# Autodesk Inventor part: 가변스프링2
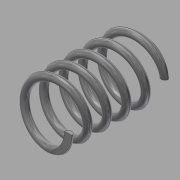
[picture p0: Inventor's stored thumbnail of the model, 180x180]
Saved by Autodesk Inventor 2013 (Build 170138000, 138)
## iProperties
Created: 2015-02
Part Number: 가변스프링2
Material: 강철, 탄소
Document SubType Name: Modeling
Designer: Administrator
Density: 7.87 g/cm^3
Mass: 18.9085 g
Surface Area: 32.5528 cm^2
Volume: 2.40261 cm^3
Author: Administrator
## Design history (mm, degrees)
sketch "스케치1"
  geometry: L1 (0, 0)-(11, 0); L2 (11, 0)-(11, 40.095); L3 (11, 40.095)-(0, 40.095); L4 (0, 40.095)-(0, 0); C1 r 1.5 at (11, 0)
  constraints: 8 end point, 2 parallel, 1 centre point, 1 coincident, 1 horizontal, 1 perpendicular
  dimensions: "d0" = 22 diameter of L2 L4; "d2" = 40.0955 distance of L1.end L2.end (derived); "d3" = 3 diameter of C1
feature "코일1" pitch "d4" = 10; turns "d6" = 5; dims "d5" = 40.0955 (= d2), "d7" = 0, angle "d8" = 90 deg, angle "d9" = 90 deg, "d10" = 0, "d11" = 0
sketch "스케치2"
  geometry: L1 (-12.5, 0)-(-9.5, 0) reference; 1 further point
  constraints: 1 horizontal alignment
extrude "돌출1" cut sketch "스케치2" stored distance "d12" = 10; taper "d13" = 0 deg
node "작업 평면1"
sketch "스케치3"
  geometry: L1 (12.5, 0)-(9.5, 0) reference; 1 further point
  constraints: 1 horizontal alignment
extrude "돌출2" cut sketch "스케치3" stored distance "d14" = 10; taper "d15" = 0 deg
node "솔리드1"
node "절단 모서리 투영1"
node "절단 모서리 투영2"
